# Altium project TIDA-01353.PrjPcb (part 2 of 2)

## Sheet TIDA-01353_EVM_Hardware.SchDoc
size 431 x 279 mm; Date: Not shown in title block; ApprovedBy: Not shown in title block; CheckedBy: Not shown in title block; Author: Not shown in title block; CompanyName: Not shown in title block; Engineer: Not shown in title block; Organization: Not shown in title block; Address1: Not shown in title block; Address2: Not shown in title block; Address3: Not shown in title block; Address4: Not shown in title block; DocumentNumber: 1; Revision: Use project parameter SCH_Rev; SheetNumber: 4; SheetTotal: 4; PageSetup: Record=PageOptions¦CenterHorizontal=True¦CenterVertical=True¦PrintScale=1.00¦XCorrection=1.00¦YCorrection=1.00¦PrintKind=0¦BorderSize=5000000¦LeftOffset=0¦BottomOffset=0¦Orientation=2¦PaperLength=1000¦PaperWidth=1000¦Scale=100¦PaperSource=15¦PrintQuality=600¦MediaType=1¦DitherType=10¦PaperKind=Letter¦PrintScaleMode=1
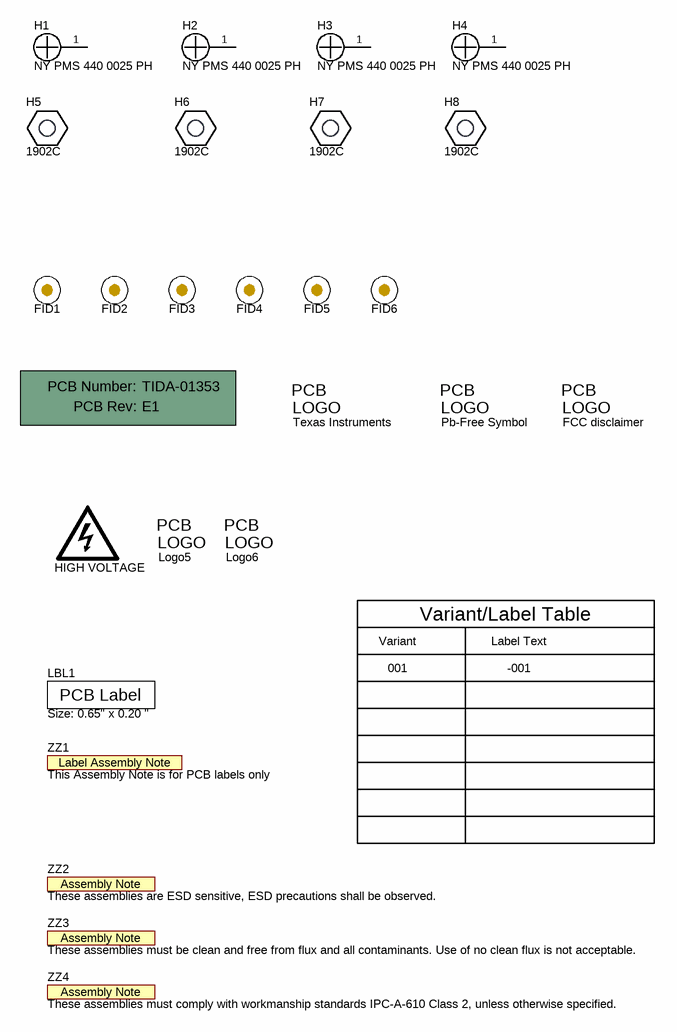
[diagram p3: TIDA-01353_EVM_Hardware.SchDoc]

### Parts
!PCB1  Printed Circuit Board  (value not drawn)  (mechanical)
FID1  Fiducial  [Fiducial10-20]  (value not drawn)
FID2  Fiducial  [Fiducial10-20]  (value not drawn)
FID3  Fiducial  [Fiducial10-20]  (value not drawn)
FID4  Fiducial  [Fiducial10-20]  (value not drawn)
FID5  Fiducial  [Fiducial10-20]  (value not drawn)
FID6  Fiducial  [Fiducial10-20]  (value not drawn)
H1  NY PMS 440 0025 PH  [NY PMS 440 0025 PH]
H2  NY PMS 440 0025 PH  [NY PMS 440 0025 PH]
H3  NY PMS 440 0025 PH  [NY PMS 440 0025 PH]
H4  NY PMS 440 0025 PH  [NY PMS 440 0025 PH]
H5  1902C  [Keystone_1902C]
H6  1902C  [Keystone_1902C]
H7  1902C  [Keystone_1902C]
H8  1902C  [Keystone_1902C]
HIGH_VOLTAGE  DANGER HIGH VOLTAGE  [IEC_HighVoltage_Large]  (value not drawn)  (no BOM)
LBL1  Size: 0.65" x 0.20 "  [Label_650x200]
Logo1  Texas Instruments  [TI_Stacked_Overlay_Medium]  (no BOM)
Logo2  Pb-Free Symbol  [Pb-Free_Overlay_Small]  (no BOM)
Logo3  FCC disclaimer  [FCC_disclaimer]  (no BOM)
Logo5  CAUTION.  READ USER GUIDE BEFORE USE  [IEC_Caution_Small]  (value not drawn)  (no BOM)
Logo6  CAUTION.  READ USER GUIDE BEFORE USE  [IEC_Caution_Small]  (value not drawn)  (no BOM)
ZZ1  This Assembly Note is for PCB labels only  [AssemblyNoteLabel]  (no BOM)
ZZ2  These assemblies are ESD sensitive, ESD precautions shall be observed.  [AssemblyNote]  (no BOM)
ZZ3  These assemblies must be clean and free from flux and all contaminants. Use of no clean flux is not acceptable.  [AssemblyNote]  (no BOM)
ZZ4  These assemblies must comply with workmanship standards IPC-A-610 Class 2, unless otherwise specified.  [AssemblyNote]  (no BOM)

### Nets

Not connected (* = marked no-connect by the designer): H1 1; H2 1; H3 1; H4 1

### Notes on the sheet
- Variant
- Variant/Label Table
- Label Text
- 001
- -001

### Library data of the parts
!PCB1 = PCB: Manufacturer: Any; PartNumber: TIDA-01353; SymbolCreator: a0412235
FID1-FID6 = Fiducial: Fiducial mark.  There is nothing to buy or mount.; SymbolCreator: codlsc
H1-H4 = NY PMS 440 0025 PH: Machine Screw, Round, #4-40 x 1/4, Nylon, Philips panhead; Manufacturer: B&F Fastener Supply; CompType: Hardware; SymbolCreator: codlsc; U/M: EA
H5-H8 = 1902C: Standoff, Hex, 0.5"L #4-40 Nylon; Manufacturer: Keystone; CompType: Hardware
HIGH_VOLTAGE = IEC_HighVoltage: IEC 61010-1 High Voltage Warning; SymbolCreator: a0412235
LBL1 = THT-14-423-10: Thermal Transfer Printable Labels, 0.650" W x 0.200" H - 10,000 per roll; Manufacturer: Brady; SymbolCreator: a0412235; CompType: Label
Logo1 = TI_Logo: Texas Instrument Corporate Signature; SymbolCreator: codlsc
Logo2 = Pb-Free: SymbolCreator: a0412235
Logo3 = FCC_disclaimer: SymbolCreator: codlsc
Logo5 Logo6 = IEC_Caution: IEC 61010-1 Caution Warning; SymbolCreator: a0412235
ZZ1 = AssemblyNoteLabel: SymbolCreator: a0412235
ZZ2-ZZ4 = AssemblyNote: SymbolCreator: codlsc

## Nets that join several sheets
3V3: TIDA-01353_System Power (6 pins), TIDA-01353_MCU and Peripherals (19 pins)
+15V: TIDA-01353_System Power (C18.1 J5.1 U6.1 U6.3), TIDA-01353_Motor Control (J12.2 J13.2 J15.2), TIDA-01353_MCU and Peripherals (R27.1)
GND: TIDA-01353_System Power (19 pins), TIDA-01353_Motor Control (20 pins), TIDA-01353_MCU and Peripherals (40 pins)
CSN: TIDA-01353_Motor Control (C67.2 R88.1), TIDA-01353_MCU and Peripherals (R45.1)
CSP: TIDA-01353_Motor Control (C67.1 R87.1), TIDA-01353_MCU and Peripherals (R39.1)
Electric_Heat: TIDA-01353_System Power (R3.1 U2.4), TIDA-01353_MCU and Peripherals (U8.37)
Enable: TIDA-01353_Motor Control (U12.4 U13.4 U14.4), TIDA-01353_MCU and Peripherals (C25.1 R32.2)
High: TIDA-01353_System Power (R6.1 U3.4), TIDA-01353_MCU and Peripherals (U8.28)
High-NoDelay: TIDA-01353_System Power (R1.1 U1.4), TIDA-01353_MCU and Peripherals (U8.23)
Low: TIDA-01353_System Power (R11.1 U5.4), TIDA-01353_MCU and Peripherals (U8.6)
Medium: TIDA-01353_System Power (R9.1 U4.4), TIDA-01353_MCU and Peripherals (U8.15)
PHU: TIDA-01353_System Power (J16.1), TIDA-01353_Motor Control (5 pins), TIDA-01353_MCU and Peripherals (R35.2)
PHV: TIDA-01353_System Power (J16.2), TIDA-01353_Motor Control (5 pins), TIDA-01353_MCU and Peripherals (R36.2)
PHW: TIDA-01353_System Power (J16.3), TIDA-01353_Motor Control (5 pins), TIDA-01353_MCU and Peripherals (R37.2)
PWM_UB: TIDA-01353_Motor Control (R68.1), TIDA-01353_MCU and Peripherals (U8.18)
PWM_UT: TIDA-01353_Motor Control (R62.1), TIDA-01353_MCU and Peripherals (U8.16)
PWM_VB: TIDA-01353_Motor Control (R69.1), TIDA-01353_MCU and Peripherals (U8.19)
PWM_VT: TIDA-01353_Motor Control (R63.1), TIDA-01353_MCU and Peripherals (U8.24)
PWM_WB: TIDA-01353_Motor Control (R82.1), TIDA-01353_MCU and Peripherals (U8.20)
PWM_WT: TIDA-01353_Motor Control (R79.1), TIDA-01353_MCU and Peripherals (U8.32)
VDC_Link: TIDA-01353_System Power (6 pins), TIDA-01353_Motor Control (6 pins), TIDA-01353_MCU and Peripherals (R38.2)

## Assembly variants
001: not fitted FID1 FID2 FID3 FID4 FID5 FID6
